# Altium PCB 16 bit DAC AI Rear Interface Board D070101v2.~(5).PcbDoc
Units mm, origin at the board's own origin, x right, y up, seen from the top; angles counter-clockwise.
Board outline 66.04 x 254 mm, 4 copper layers (Top Layer, InternalPlane1, InternalPlane2, Bottom Layer), stack 1.554 mm thick; 6 components, 34 nets, 183 pads, 15 vias.
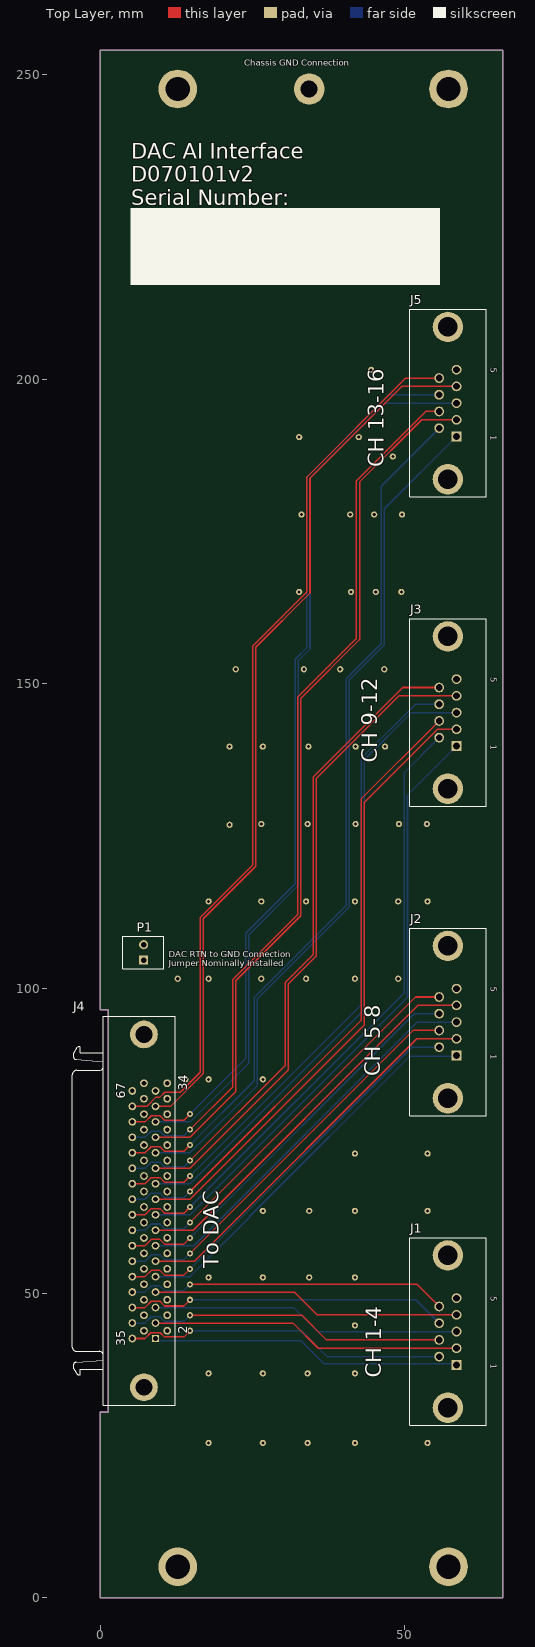
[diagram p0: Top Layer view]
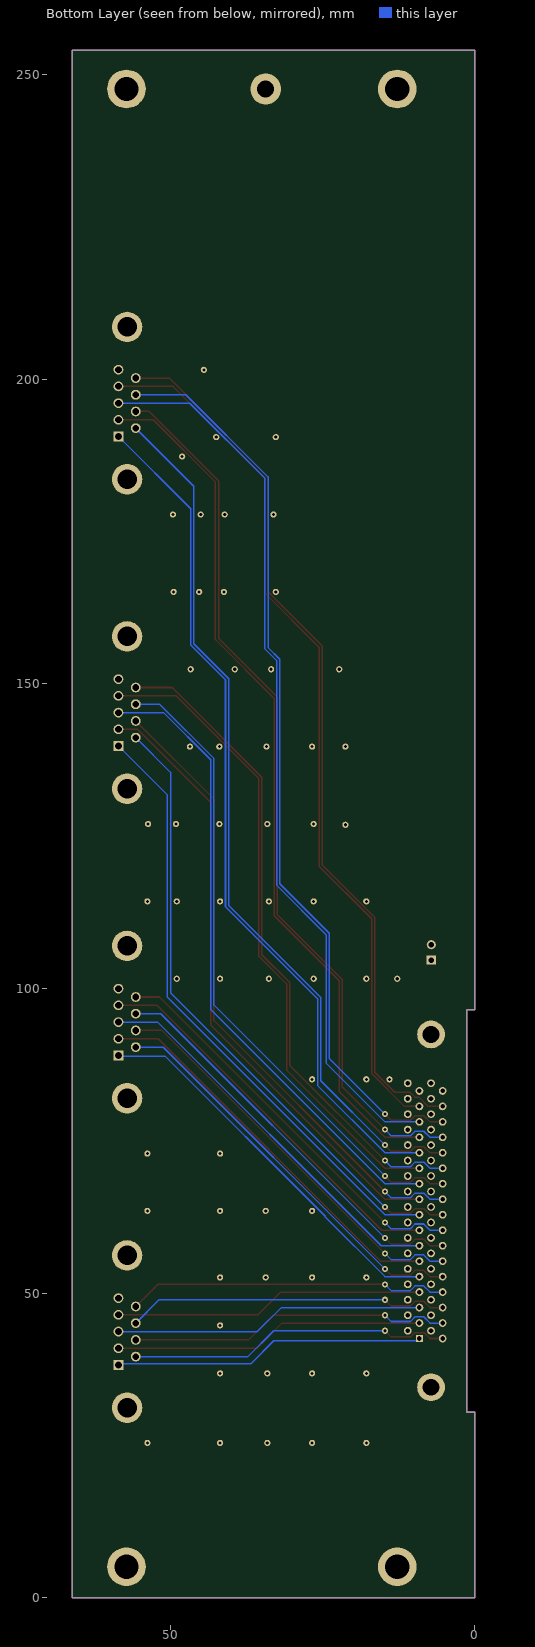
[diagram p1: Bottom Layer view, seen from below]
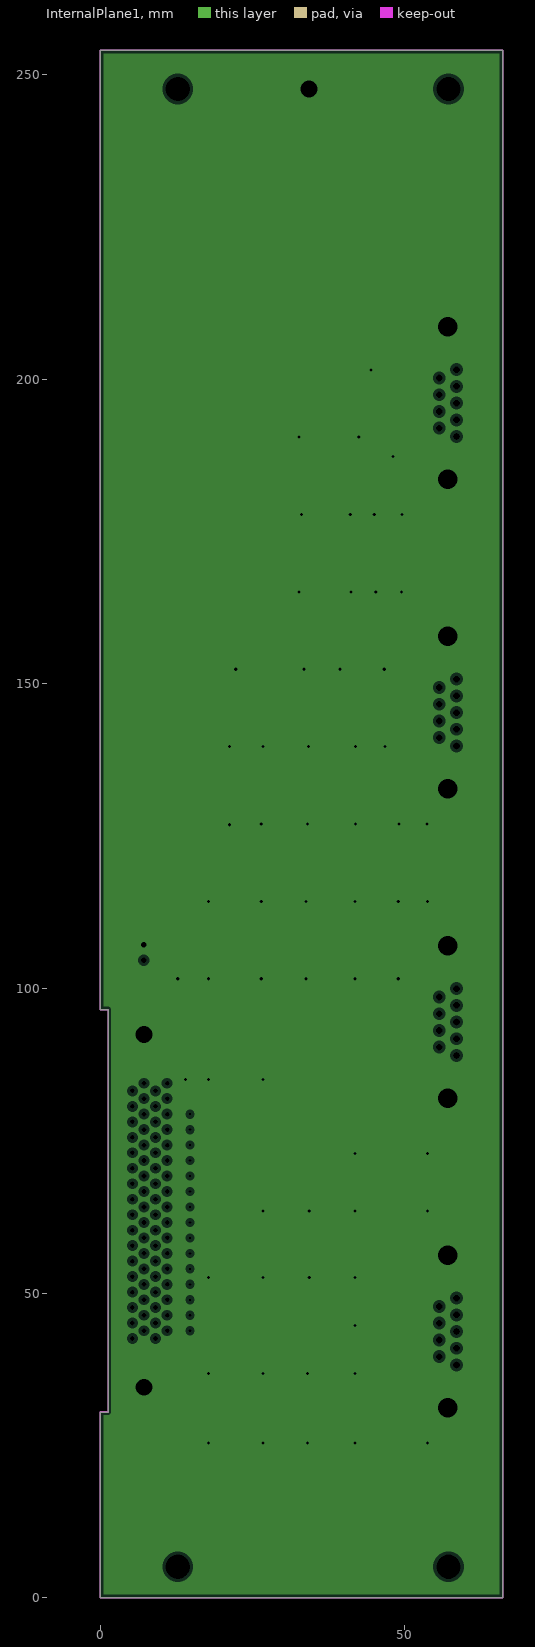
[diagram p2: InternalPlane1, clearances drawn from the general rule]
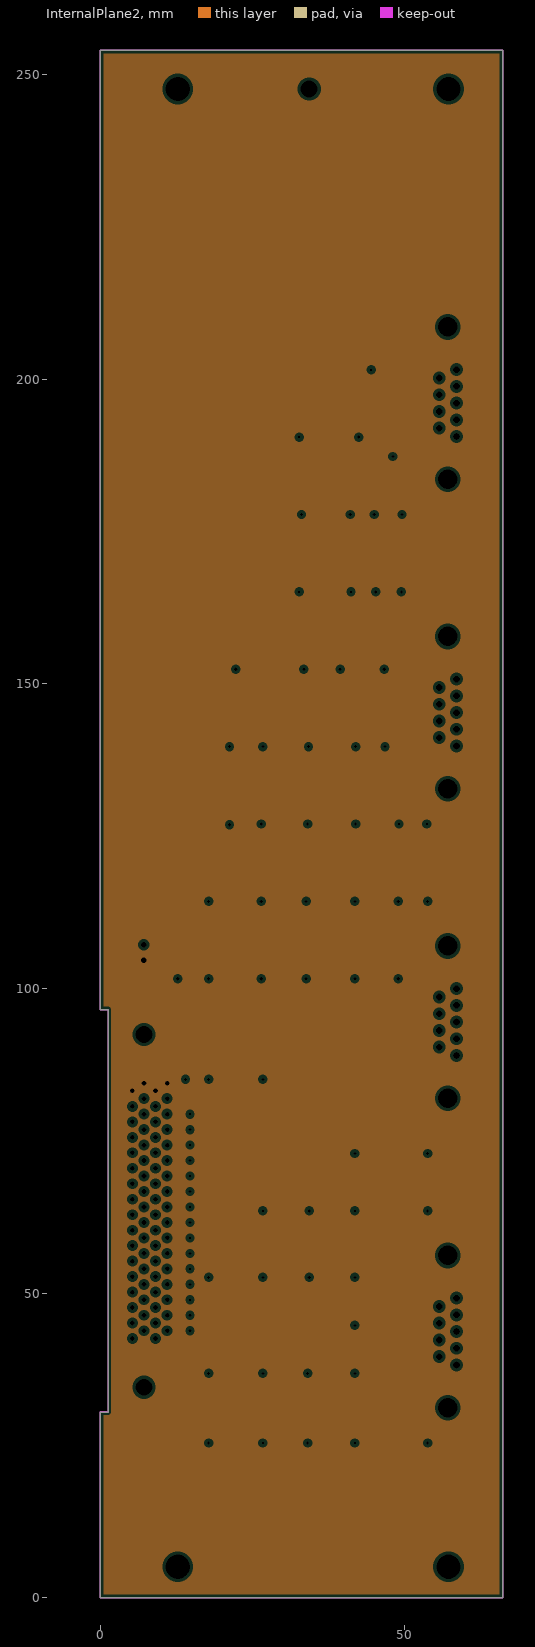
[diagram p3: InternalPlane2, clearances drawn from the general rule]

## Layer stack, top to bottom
Top Solder: solder mask 0.0102, Solder Resist, Dk 3.5
Top Layer: signal copper 0.0356
Dielectric1: core 0.254, FR-4, Dk 4.8
InternalPlane1: plane copper 0.0356, net GND
Dielectric2: prepreg 0.9042, FR-4, Dk 4.8
InternalPlane2: plane copper 0.0356, net INPUTRTN
Dielectric3: core 0.254, FR-4, Dk 4.8
Bottom Layer: signal copper 0.0356
Bottom Solder: solder mask 0.0102, Solder Resist, Dk 3.5

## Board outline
0,0 0,30.48 1.27,30.48 1.27,96.52 0,96.52 0,254 66.04,254 66.04,0

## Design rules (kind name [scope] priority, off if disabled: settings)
Clearance [All] p1: gap=0.254 ignorepadtopadclearanceinfootprint=FALSE except(0: Arc-Hole Track-Hole SMDPad-Hole THPad-Hole Via-Hole Fill-Hole Poly-Hole Region-Hole Text-Hole)
FabricationTestPointUsage TestPointUsage [All] p1: valid=0 allowmultiple=FALSE
FabricationTestpoint Testpoint [All] p1: side=3 testpointundercomponent=TRUE minsize=1.016 maxsize=2.54 preferedsize=1.524 minholesize=0 maxholesize=1.016 preferedholesize=0.813 testpointgrid=0.025 allowsidetop=TRUE allowsidebottom=TRUE usegrid=TRUE gridtolerance=0
HoleSize [All] p1: absolutevalues=TRUE maxlimit=5.08 minlimit=0.025 maxpercent=80.000 minpercent=20.000
PlaneClearance [All] p1: clearance=0.508
PlaneConnect [All] p1: planeconnectstyle=Relief reliefexpansion=0.508 reliefentries=4 reliefconductorwidth=0.254 reliefairgap=0.254
PolygonConnect [All] p1: connectstyle=Relief reliefconductorwidth=0.254 reliefentries=4 polygonreliefangle="90 Angle" airgapwidth=0.254
RoutingVias [All] p1: holewidth=0.508 width=1.016 viastyle="Through Hole" minholewidth=0.508 minwidth=1.016 maxholewidth=0.711 maxwidth=1.27
SolderMaskExpansion [All] p1: expansion=0.102
Width [All] p1: maxlimit=2.54 minlimit=0.254 preferedwidth=0.254
25 further rules are at their usual default settings.

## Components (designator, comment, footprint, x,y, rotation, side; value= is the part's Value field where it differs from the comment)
J1 "D9F" D9F 57.048,43.688 r270 top
J2 "D9F" D9F 57.048,94.488 r270 top
J3 "D9F" D9F 57.048,145.288 r270 top
J4 "787082-7" 787082-7 0.508,63.5 r90 top
J5 "D9F" D9F 57.048,196.088 r270 top
P1 "Header 2" HDR1X2 7.112,104.648 r90 top

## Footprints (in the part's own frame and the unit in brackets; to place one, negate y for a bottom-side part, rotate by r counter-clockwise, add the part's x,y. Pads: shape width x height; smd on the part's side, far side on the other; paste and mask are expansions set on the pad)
787082-7 [mm] "Connector; D Subminiature 050 Series; 68 Position; Right Angle"
  rect 1.143x1.143 hole 0.762: 1(-20.955,-8.555)
  round 1.27 hole 0.762: 2(-19.685,-10.46) 3(-18.415,-8.555) 4(-17.145,-10.46) 5(-15.875,-8.555) 6(-14.605,-10.46) 7(-13.335,-8.555) 8(-12.065,-10.46) 9(-10.795,-8.555) 10(-9.525,-10.46) 11(-8.255,-8.555) 12(-6.985,-10.46) 13(-5.715,-8.555) 14(-4.445,-10.46) 15(-3.175,-8.555) 16(-1.905,-10.46) 17(-0.635,-8.555) 18(0.635,-10.46) 19(1.905,-8.555) 20(3.175,-10.46) 21(4.445,-8.555) 22(5.715,-10.46) 23(6.985,-8.555) 24(8.255,-10.46) 25(9.525,-8.555) 26(10.795,-10.46) 27(12.065,-8.555) 28(13.335,-10.46) 29(14.605,-8.555) 30(15.875,-10.46) 31(17.145,-8.555) 32(18.415,-10.46) 33(19.685,-8.555) 34(20.955,-10.46) 35(-20.955,-4.745) 36(-19.685,-6.65) 37(-18.415,-4.745) 38(-17.145,-6.65) 39(-15.875,-4.745) 40(-14.605,-6.65) 41(-13.335,-4.745) 42(-12.065,-6.65) 43(-10.795,-4.745) 44(-9.525,-6.65) 45(-8.255,-4.745) 46(-6.985,-6.65) 47(-5.715,-4.745) 48(-4.445,-6.65) 49(-3.175,-4.745) 50(-1.905,-6.65) 51(-0.635,-4.745) 52(0.635,-6.65) 53(1.905,-4.745) 54(3.175,-6.65) 55(4.445,-4.745) 56(5.715,-6.65) 57(6.985,-4.745) 58(8.255,-6.65) 59(9.525,-4.745) 60(10.795,-6.65) 61(12.065,-4.745) 62(13.335,-6.65) 63(14.605,-4.745) 64(15.875,-6.65) 65(17.145,-4.745) 66(18.415,-6.65) 67(19.685,-4.745) 68(20.955,-6.65)
  round 4.55 hole 2.77: 69(-28.955,-6.65) 70(28.955,-6.65)
  silkscreen extent -31.95,-11.76 31.95,5.11, body extent -31.94,-11.8 31.94,5.07, height 9.49
D9F [mm]
  rect 1.6x1.6 hole 1.1: 1(5.486,1.422)
  round 1.6 hole 1.1: 2(2.743,1.422) 3(0.005,1.422) 4(-2.743,1.422) 5(-5.486,1.422) 6(4.115,-1.422) 7(1.372,-1.422) 8(-1.372,-1.422) 9(-4.115,-1.422)
  round 5 hole 3.2: 10(-12.497,0) 11(12.497,0)
  silkscreen extent -15.4,-6.3 15.4,6.3, body extent -15.4,-6.3 15.41,6.3, height 12.18
HDR1X2 [mm] "Connector; Header; 2 Position"
  rect 1.5x1.5 hole 0.9: 1(0,0)
  round 1.5 hole 0.9: 2(2.54,0)
  silkscreen extent -1.4,-3.3 3.94,3.43, body extent -1.19,-3.1 3.73,3.25, height 10.68

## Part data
J1 J2 J3 J5: "9 Position D-Sub Receptacle, Female Sockets Connector", Case/Package=Metal, Color=Black, Current Rating=6A, Flammability Rating="UL94 V-0", Manufacturer="TE Connectivity", Manufacturer Part Number=5747150-7, Max Operating Temperature=105°C, Max Supply Voltage (AC)=250V, Max Voltage Rating (DC)=250.25kV, Min Operating Temperature=-55°C, Package Quantity=17, Supplier Part Number 1=A34073-ND, Voltage Rating=125V
J4: library part "D68F 90deg", "68 Position D-Type Receptacle, Female Sockets Connector", Color=Black, Current Rating=1A, Flammability Rating="UL94 V-0", Manufacturer="TE Connectivity", Manufacturer Part Number=7870827, Max Operating Temperature=105°C, Min Operating Temperature=-55°C, Package Quantity=8, Supplier Part Number 1=A3321-ND, Voltage Rating=30V
P1: "Connector Header Through Hole 2 position 0.100\" (2.54mm)", Color=White, Contact Resistance=10mR, Current Rating=4A, Flammability Rating="UL94 V-0", Insulation Resistance=500GR, Manufacturer=Molex, Manufacturer Part Number=22-23-2021, Max Operating Temperature=75°C, Min Operating Temperature=0°C, Package Quantity=3000, Supplier Part Number 1=WM4200-ND, Voltage Rating=250V

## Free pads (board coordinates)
  round 5.08 hole 2.794: 0(34.29,247.65)
  round 6.35 hole 4: 0(57.15,5.08) 1(57.15,247.65) 2(12.7,247.65) 3(12.7,5.08)
  round 1.016 hole 0.508: 5(41.783,36.83) 6(53.721,25.4) 7(41.783,44.704) 8(41.783,25.4) 9(17.78,36.83) 10(26.67,52.578) 11(41.783,52.578) 12(26.67,25.4) 13(17.78,25.4) 14(26.67,63.5) 15(41.783,63.5) 16(53.721,72.898) 21(26.67,85.09) 22(34.29,63.5) 23(17.78,85.09) 24(17.78,52.578) 25(13.97,85.09) 26(17.78,101.6) 27(26.416,101.6) 28(33.782,101.6) 29(41.783,101.6) 30(48.895,101.6) 32(41.783,72.898) 36(34.036,25.4) 36(34.036,36.83) 36(34.29,52.578) 37(26.416,114.3) 38(33.782,114.3) 39(41.783,114.3) 40(48.895,114.3) 41(49.022,127) 42(41.91,127) 43(34.036,127) 44(26.416,127) 45(21.209,126.873) 46(17.78,114.3) 47(12.7,101.6) 48(21.209,139.7) 49(26.67,139.7) 50(34.163,139.7) 51(41.91,139.7) 52(46.736,139.7) 53(46.609,152.4) 54(39.37,152.4) 55(33.401,152.4) 56(22.225,152.4) 57(41.148,165.1) 58(45.212,165.1) 59(49.403,165.1) 60(32.639,165.1) 61(33.02,177.8) 62(41.021,177.8) 63(44.958,177.8) 64(49.53,177.8) 65(48.006,187.325) 66(42.418,190.5) 67(32.639,190.5) 68(44.45,201.549) 69(53.721,114.3) 70(53.594,127) 71(53.721,63.5) 75(26.67,36.83)

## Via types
v1: diameter 1.016, hole 0.508, Top Layer to Bottom Layer, 15 vias

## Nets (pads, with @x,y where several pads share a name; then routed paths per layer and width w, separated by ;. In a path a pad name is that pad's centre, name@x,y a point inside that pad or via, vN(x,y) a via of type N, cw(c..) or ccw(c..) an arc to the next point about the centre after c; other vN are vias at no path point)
GND: J1.10 J1.11 J2.10 J2.11 J3.10 J3.11 J4.69 J4.70 J5.10 J5.11 P1.2 pad.0@34.29,247.65 pad.5 pad.6 pad.7 pad.8 pad.9 pad.10 pad.11 pad.12 pad.13 pad.14 pad.15 pad.16 pad.21 pad.22 pad.23 pad.24 pad.25 pad.26 pad.27 pad.28 pad.29 pad.30 pad.32 pad.36 pad.37 pad.38 pad.39 pad.40 pad.41 pad.42 pad.43 pad.44 pad.45 pad.46 pad.47 pad.48 pad.49 pad.50 pad.51 pad.52 pad.53 pad.54 pad.55 pad.56 pad.57 pad.58 pad.59 pad.60 pad.61 pad.62 pad.63 pad.64 pad.65 pad.66 pad.67 pad.68 pad.69 pad.70 pad.71 pad.75
INPUTN1: J1.6 J4.35 | length 53.3
  Top Layer w0.254: J4.35 7.325,42.545 8.277,43.498 9.849,43.498 10.547,42.799 13.716,42.799 v1(14.732,43.815)
  Bottom Layer w0.254: v1(14.732,43.815) 32.979,43.815 37.221,39.573 55.55,39.573 J1.6@55.626,39.497
INPUTN2: J1.7 J4.37 | length 53.2
  Top Layer w0.254: v1(14.732,46.355) 33.081,46.355 37.119,42.316 55.575,42.316 J1.7@55.626,42.266
  Bottom Layer w0.254: J4.37 7.325,45.085 8.341,46.101 9.785,46.101 10.547,45.339 13.716,45.339 v1(14.732,46.355)
INPUTN3: J1.8 J4.39 | length 53.1
  Top Layer w0.254: J4.39 7.325,47.625 8.341,48.641 9.785,48.641 10.547,47.879 13.716,47.879 v1(14.732,48.895)
  Bottom Layer w0.254: v1(14.732,48.895) 51.791,48.895 J1.8
INPUTN4: J1.9 J4.41 | length 53
  Top Layer w0.254: v1(14.732,51.435) 51.994,51.435 J1.9
  Bottom Layer w0.254: J4.41 7.325,50.165 8.341,51.181 9.785,51.181 10.547,50.419 13.716,50.419 v1(14.732,51.435)
INPUTN5: J2.6 J4.43 | length 66.6
  Top Layer w0.254: J4.43 7.325,52.705 8.341,53.721 9.785,53.721 10.547,52.959 13.716,52.959 v1(14.732,53.975)
  Bottom Layer w0.254: v1(14.732,53.975) 51.13,90.373 55.55,90.373 J2.6@55.626,90.297
INPUTN6: J2.7 J4.45 | length 66.7
  Top Layer w0.254: v1(14.732,56.515) 51.333,93.116 55.575,93.116 J2.7@55.626,93.066
  Bottom Layer w0.254: J4.45 7.325,55.245 8.341,56.261 9.785,56.261 10.547,55.499 13.716,55.499 v1(14.732,56.515)
INPUTN7: J2.8 J4.47 | length 66.8
  Top Layer w0.254: J4.47 7.325,57.785 8.341,58.801 9.785,58.801 10.547,58.039 13.716,58.039 v1(14.732,59.055)
  Bottom Layer w0.254: v1(14.732,59.055) 51.537,95.86 55.601,95.86 J2.8@55.626,95.834
INPUTN8: J2.9 J4.49 | length 66.9
  Top Layer w0.254: v1(14.732,61.595) 51.74,98.603 J2.9
  Bottom Layer w0.254: J4.49 7.325,60.325 8.341,61.341 9.785,61.341 10.547,60.579 13.716,60.579 v1(14.732,61.595)
INPUTN9: J3.6 J4.51 | length 104.7
  Top Layer w0.254: J4.51 7.325,62.865 8.341,63.881 9.785,63.881 10.547,63.119 13.716,63.119 14.605,64.008 v1@14.859,64.008
  Bottom Layer w0.254: v1@14.859,64.008 14.859,64.262 49.911,99.314 49.911,135.458 55.55,141.097 J3.6@55.626,141.097
  other v1: 14.732,64.135
INPUTN10: J3.7 J4.53 | length 104.9
  Top Layer w0.254: v1@14.757,66.599 14.757,66.7 42.799,94.742 42.799,131.089 55.575,143.866 J3.7@55.626,143.866
  Bottom Layer w0.254: J4.53 7.325,65.405 8.341,66.421 9.785,66.421 10.547,65.659 13.716,65.659 14.656,66.599 v1@14.757,66.599
  other v1: 14.732,66.675
INPUTN11: J3.8 J4.55 | length 107.4
  Top Layer w0.254: J4.55 7.325,67.945 8.341,68.961 9.785,68.961 10.547,68.199 13.716,68.199 14.605,69.088 v1@14.732,69.088
  Bottom Layer w0.254: v1@14.732,69.088 v1(14.732,69.215) 42.799,97.282 42.799,137.739 51.72,146.66 55.601,146.66 J3.8@55.626,146.634
INPUTN12: J3.9 J4.57 | length 108.8
  Top Layer w0.254: v1@14.732,71.628 v1(14.732,71.755) 30.353,87.376 30.353,100.965 34.925,105.537 34.925,134.691 49.637,149.403 J3.9
  Bottom Layer w0.254: J4.57 7.325,70.485 8.341,71.501 9.785,71.501 10.547,70.739 13.716,70.739 14.605,71.628 v1@14.732,71.628
INPUTN13: J4.59 J5.6 | length 145.3
  Top Layer w0.254: J4.59 7.325,73.025 8.341,74.041 9.785,74.041 10.547,73.279 13.716,73.279 v1@14.605,74.168
  Bottom Layer w0.254: v1@14.605,74.168 v1(14.732,74.295) 25.273,84.836 25.273,98.534 40.361,113.621 40.361,150.851 46.101,156.591 46.101,182.448 J5.6
INPUTN14: J4.61 J5.7 | length 146.8
  Top Layer w0.254: v1(14.732,76.835) 21.717,83.82 21.717,101.473 32.385,112.141 32.385,147.828 42.037,157.48 42.037,183.332 53.422,194.716 55.575,194.716 J5.7@55.626,194.666
  Bottom Layer w0.254: J4.61 7.325,75.565 8.341,76.581 9.785,76.581 10.547,75.819 13.716,75.819 14.483,76.586 v1@14.483,76.957
INPUTN15: J4.63 J5.8 | length 149.9
  Top Layer w0.254: J4.63 7.325,78.105 8.341,79.121 9.785,79.121 10.547,78.359 13.716,78.359 v1(14.732,79.375)
  Bottom Layer w0.254: 15.113,79.756 23.876,88.519 23.876,109.049 32.004,117.177 32.004,154.051 33.909,155.956 33.909,183.967 47.402,197.46 55.601,197.46 J5.8@55.626,197.434
INPUTN16: J4.65 J5.9 | length 146.9
  Top Layer w0.254: J4.65 7.626,80.645 9.15,82.169 9.785,82.169 10.587,82.971 13.108,82.971 16.383,86.246 16.383,111.646 25.019,120.282 25.019,156.223 33.909,165.113 33.909,183.967 50.145,200.203 J5.9
INPUTP1: J1.1 J4.1 | length 51.2
  Bottom Layer w0.254: J4.1 9.444,42.164 32.956,42.164 36.728,38.392 58.28,38.392 J1.1
INPUTP2: J1.2 J4.3 | length 51.1
  Top Layer w0.254: J4.3 31.619,45.085 35.759,40.945 58.344,40.945 J1.2@58.42,40.869
INPUTP3: J1.3 J4.5 | length 51
  Bottom Layer w0.254: J4.5 31.72,47.625 35.662,43.683 58.374,43.683 J1.3@58.42,43.637
INPUTP4: J1.4 J4.7 | length 50.9
  Top Layer w0.254: J4.7 31.822,50.165 35.556,46.431 58.395,46.431 J1.4@58.42,46.406
INPUTP5: J2.1 J4.9 | length 64.4
  Bottom Layer w0.254: J4.9 14.719,52.705 24.511,62.497 24.511,62.598 50.813,88.9 J2.1@58.42,88.9
INPUTP6: J2.2 J4.11 | length 64.5
  Top Layer w0.254: J4.11 15.439,55.245 51.939,91.745 58.344,91.745 J2.2@58.42,91.669
INPUTP7: J2.3 J4.13 | length 64.6
  Bottom Layer w0.254: J4.13 15.337,57.785 52.035,94.483 J2.3
INPUTP8: J2.4 J4.15 | length 64.7
  Top Layer w0.254: J4.15 15.236,60.325 52.142,97.231 J2.4
INPUTP9: J3.1 J4.17 | length 100.7
  Bottom Layer w0.254: J4.17 14.719,62.865 50.419,98.565 50.419,131.75 J3.1
INPUTP10: J3.2 J4.19 | length 102.7
  Top Layer w0.254: J4.19 14.719,65.405 43.307,93.993 43.307,130.524 55.327,142.545 58.344,142.545 J3.2@58.42,142.469
INPUTP11: J3.3 J4.21 | length 105.4
  Bottom Layer w0.254: J4.21 14.719,67.945 43.307,96.533 43.307,137.528 51.062,145.283 58.374,145.283 J3.3@58.42,145.237
INPUTP12: J3.4 J4.23 | length 106.8
  Top Layer w0.254: J4.23 14.719,70.485 30.861,86.627 30.861,100.755 35.433,105.327 35.433,134.48 48.984,148.031 58.395,148.031 J3.4@58.42,148.006
INPUTP13: J4.25 J5.1 | length 141.4
  Bottom Layer w0.254: J4.25 14.719,73.025 25.781,84.087 25.781,98.323 40.894,113.436 40.894,150.666 46.609,156.381 46.609,178.74 J5.1
INPUTP14: J4.27 J5.2 | length 144.9
  Top Layer w0.254: J4.27 14.719,75.565 22.225,83.071 22.225,101.263 32.893,111.931 32.893,147.618 42.545,157.27 42.545,183.121 52.769,193.345 58.344,193.345 J5.2@58.42,193.269
INPUTP15: J4.29 J5.3 | length 148.6
  Bottom Layer w0.254: J4.29 14.719,78.105 24.384,87.77 24.384,108.839 32.512,116.967 32.512,153.841 34.417,155.746 34.417,183.756 46.744,196.083 58.425,196.083 J5.3@58.471,196.037
INPUTP16: J4.31 J5.4 | length 145.3
  Top Layer w0.254: J4.31 11.501,80.645 16.891,86.035 16.891,111.435 25.527,120.071 25.527,156.012 34.417,164.902 34.417,183.756 49.492,198.831 58.395,198.831 J5.4@58.42,198.806
INPUTRTN: J4.33 J4.34 J4.67 J4.68 P1.1
pads on no net: J1.5 J2.5 J3.5 J4.2 J4.4 J4.6 J4.8 J4.10 J4.12 J4.14 J4.16 J4.18 J4.20 J4.22 J4.24 J4.26 J4.28 J4.30 J4.32 J4.36 J4.38 J4.40 J4.42 J4.44 J4.46 J4.48 J4.50 J4.52 J4.54 J4.56 J4.58 J4.60 J4.62 J4.64 J4.66 J5.5

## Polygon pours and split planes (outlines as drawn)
GND on InternalPlane1 (split plane): 65.53,0.51 0.51,0.51 0.51,29.97 1.27,29.97 1.37,29.979 1.465,30.008 1.554,30.056 1.631,30.119 1.694,30.196 1.742,30.285 1.771,30.38 1.78,30.48 1.78,96.52 1.771,96.62 1.742,96.715 1.694,96.804 1.631,96.881 1.554,96.944 1.465,96.992 1.37,97.021 1.27,97.03 0.51,97.03 0.51,253.49 65.53,253.49
INPUTRTN on InternalPlane2 (split plane): 65.53,0.51 0.51,0.51 0.51,29.97 1.27,29.97 1.37,29.979 1.465,30.008 1.554,30.056 1.631,30.119 1.694,30.196 1.742,30.285 1.771,30.38 1.78,30.48 1.78,96.52 1.771,96.62 1.742,96.715 1.694,96.804 1.631,96.881 1.554,96.944 1.465,96.992 1.37,97.021 1.27,97.03 0.51,97.03 0.51,253.49 65.53,253.49

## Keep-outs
Keep-Out Layer:
  the board outline again, w0.254

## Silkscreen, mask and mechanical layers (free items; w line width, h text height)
Top Overlay:
  rectangle: 4.928,215.443 55.728,228.143
  text "Chassis GND Connection" at 23.622,251.46 h1.02
  text "DAC AI Interface / D070101v2 / Serial Number:" at 5.08,228.6 h2.54
  text "CH 13-16" at 46.482,185.547 h2.54 r90
  text "CH 9-12" at 45.466,137.033 h2.54 r90
  text "DAC RTN to GND Connection / Jumper Nominally Installed" at 11.201,103.632 h1.02
  text "CH 5-8" at 45.974,85.598 h2.54 r90
  text "To DAC" at 19.431,54.102 h2.54 r90
  text "CH 1-4" at 46.101,36.068 h2.54 r90
Mechanical 1:
  lines w0.254: 0,0 0,30.48 1.27,30.48 1.27,63.5 1.27,96.52 0,96.52 0,254 66.04,254 66.04,0 0,0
